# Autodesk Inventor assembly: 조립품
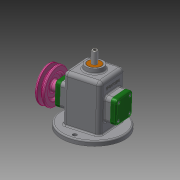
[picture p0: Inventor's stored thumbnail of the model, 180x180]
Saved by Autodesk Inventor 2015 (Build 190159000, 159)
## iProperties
Created: 2021-08
Part Number: 조립품
Document SubType Name: Assembly
Designer: 10401
Author: 10401
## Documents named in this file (16)
- C:\Users\10401\Desktop\710806v1001\조립품.iam
- C:\Users\10401\Desktop\710806v1001\V벨트풀리.ipt
- C:\Users\10401\Desktop\710806v1001\고정핀 1.2x8.ipt
- C:\Users\10401\Desktop\710806v1001\뒤커버.ipt
- C:\Users\10401\Desktop\710806v1001\링크.ipt
- C:\Users\10401\Desktop\710806v1001\멈춤나사 M3x8.ipt
- C:\Users\10401\Desktop\710806v1001\베어링 12x32x10.ipt
- C:\Users\10401\Desktop\710806v1001\본체.ipt
- C:\Users\10401\Desktop\710806v1001\볼트 M4.ipt
- C:\Users\10401\Desktop\710806v1001\부시.ipt
- C:\Users\10401\Desktop\710806v1001\슬라이드.ipt
- C:\Users\10401\Desktop\710806v1001\앞커버.ipt
- C:\Users\10401\Desktop\710806v1001\오일 실 12 25 7.ipt
- C:\Users\10401\Desktop\710806v1001\키 4x4x10.ipt
- C:\Users\10401\Desktop\710806v1001\편심축.ipt
- C:\Users\10401\Desktop\710806v1001\핀 5x18.ipt
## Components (3 placed, 3 different names)
1. V벨트풀리:1 — 각도:2
2. 고정핀 1.2x8:1
3. 핀 5x18:1
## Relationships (1: Angle 1)
- 각도:2 [Angle]: V벨트풀리:1
